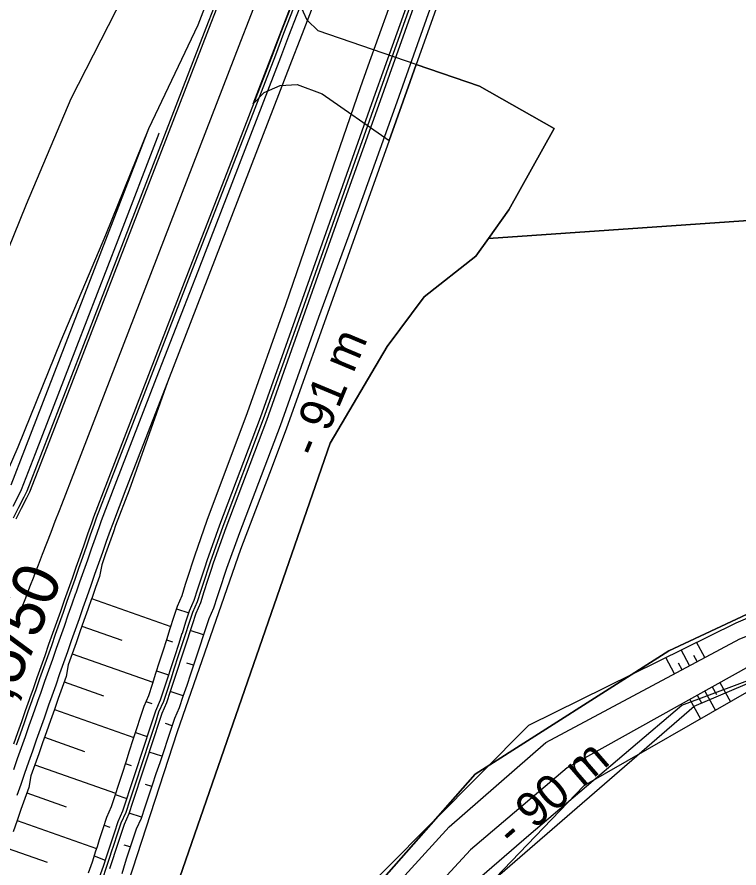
# Model space of a CAD drawing. Extents: x -440566 to -438466, y -1132677 to -1129707.
# Drawn here: x -439601.1 to -439538.1, y -1130370 to -1130295.8 of the extents above; entities that cross this region are included whole.
import ezdxf

# ---------------------------------------------------------------- set-up
doc = ezdxf.new("R2010")
doc.units = 0
for name, color, linetype in [('Vrstva 1', 7, 'Continuous'), ('Vrstva 10', 7, 'Continuous'), ('Vrstva 11', 7, 'Continuous'), ('Vrstva 15', 7, 'Continuous'), ('Vrstva 2', 7, 'Continuous'), ('Vrstva 3', 7, 'Continuous'), ('Vrstva 4', 7, 'Continuous'), ('Vrstva 52', 7, 'Continuous'), ('Vrstva 8', 7, 'Continuous'), ('Vrstva 9', 7, 'Continuous')]:
    doc.layers.add(name, color=color, linetype=linetype)

msp = doc.modelspace()

# ---------------------------------------------------------------- linework, layer by layer
at = {"layer": 'Vrstva 1'}
msp.add_circle((-439546.225, -1130326.068), 100.196, dxfattribs=at)
at = {"layer": 'Vrstva 10'}
for p, q in [((-439541.116, -1130351.662), (-439541.828, -1130350.33)), ((-439542.44, -1130352.37), (-439543.172, -1130350.994)), ((-439543.764, -1130353.076), (-439544.52, -1130351.66)), ((-439543.1, -1130352.722), (-439543.4, -1130352.166)), ((-439541.778, -1130352.016), (-439542.068, -1130351.474)), ((-439540.468, -1130354.218), (-439540.094, -1130354.89)), ((-439539.814, -1130353.854), (-439538.882, -1130355.522)), ((-439541.778, -1130354.95), (-439541.4, -1130355.626)), ((-439541.122, -1130354.586), (-439540.182, -1130356.268)), ((-439542.434, -1130355.318), (-439541.484, -1130357.014))]:
    msp.add_line(p, q, dxfattribs=at)
at = {"layer": 'Vrstva 11'}
for points in [[(-439614.54, -1130393.736), (-439602.886, -1130391.502), (-439590.194, -1130387.786), (-439581.31, -1130382.686), (-439571.73, -1130375.574), (-439563.408, -1130366.438), (-439554.968, -1130359.058), (-439538.066, -1130350.036), (-439518.176, -1130342.266)], [(-439517.844, -1130344.818), (-439537.232, -1130352.412), (-439553.102, -1130361.278), (-439561.554, -1130368.442), (-439569.834, -1130377.42), (-439579.582, -1130385.476), (-439589.25, -1130390.818), (-439602.494, -1130394.582), (-439614.18, -1130396.886)]]:
    msp.add_lwpolyline(points, dxfattribs=at)
at = {"layer": 'Vrstva 15'}
for p, q in [((-439594.569, -1130346.526), (-439587.676, -1130348.955)), ((-439587.182, -1130347.413), (-439586.104, -1130347.758)), ((-439595.418, -1130348.935), (-439591.938, -1130350.161)), ((-439584.822, -1130349.679), (-439585.975, -1130349.298)), ((-439588.05, -1130350.118), (-439587.518, -1130350.292)), ((-439596.268, -1130351.345), (-439589.241, -1130353.817)), ((-439585.701, -1130352.335), (-439586.272, -1130352.148)), ((-439588.92, -1130352.822), (-439587.869, -1130353.172)), ((-439596.972, -1130353.794), (-439593.544, -1130355.004)), ((-439586.581, -1130354.991), (-439587.713, -1130354.623)), ((-439589.842, -1130355.508), (-439589.322, -1130355.684)), ((-439597.821, -1130356.204), (-439590.902, -1130358.643)), ((-439587.56, -1130357.609), (-439588.119, -1130357.429)), ((-439598.67, -1130358.613), (-439595.18, -1130359.843)), ((-439590.757, -1130358.196), (-439589.735, -1130358.548)), ((-439588.445, -1130360.263), (-439589.552, -1130359.91)), ((-439599.52, -1130361.023), (-439592.479, -1130363.502)), ((-439591.633, -1130360.899), (-439591.129, -1130361.076)), ((-439589.331, -1130362.917), (-439589.879, -1130362.744)), ((-439600.224, -1130363.472), (-439596.792, -1130364.684)), ((-439592.511, -1130363.601), (-439591.515, -1130363.957)), ((-439590.22, -1130365.57), (-439591.304, -1130365.23)), ((-439601.073, -1130365.882), (-439594.152, -1130368.324)), ((-439593.481, -1130366.268), (-439592.991, -1130366.447)), ((-439601.922, -1130368.291), (-439598.444, -1130369.518)), ((-439591.206, -1130368.185), (-439591.741, -1130368.019)), ((-439594.363, -1130368.969), (-439593.397, -1130369.328))]:
    msp.add_line(p, q, dxfattribs=at)
at = {"layer": 'Vrstva 4'}
for points in [[(-439566.273, -1130299.951), (-439560.765, -1130301.836), (-439554.249, -1130305.538), (-439558.213, -1130312.615), (-439559.98, -1130315.123), (-439525.556, -1130312.748), (-439529.11, -1130305.49), (-439530.87, -1130301.89), (-439532.13, -1130291.95), (-439535.1, -1130272.62), (-439536.48, -1130264.88), (-439536.79, -1130262.95), (-439538.61, -1130253.25), (-439540.53, -1130243.61), (-439541.61, -1130240.34), (-439543.65, -1130245.48), (-439548.81, -1130256.72), (-439549.41, -1130258.02), (-439556.03, -1130271.21), (-439566.273, -1130299.951)], [(-439568.638, -1130306.589), (-439566.8, -1130301.43), (-439566.273, -1130299.951), (-439574.836, -1130297.021), (-439575.782, -1130296.084), (-439576.419, -1130294.674), (-439576.553, -1130293.141), (-439580.519, -1130303.402), (-439579.519, -1130302.403), (-439578.137, -1130301.772), (-439576.639, -1130301.685), (-439574.478, -1130302.52), (-439568.638, -1130306.589)], [(-439559.98, -1130315.123), (-439558.213, -1130312.615), (-439554.249, -1130305.538), (-439560.765, -1130301.836), (-439566.273, -1130299.951), (-439566.8, -1130301.43), (-439568.638, -1130306.589), (-439573.14, -1130319.23), (-439577.57, -1130331.65), (-439578.84, -1130335), (-439581.59, -1130342.25), (-439587.1, -1130358.13), (-439593.34, -1130377.27)], [(-439588.419, -1130375.264), (-439573.789, -1130332.956), (-439568.805, -1130324.53), (-439565.58, -1130320.223), (-439561.071, -1130316.673), (-439559.98, -1130315.123), (-439558.213, -1130312.615), (-439554.249, -1130305.538), (-439560.765, -1130301.836), (-439566.273, -1130299.951), (-439566.8, -1130301.43), (-439568.638, -1130306.589)], [(-439568.638, -1130306.589), (-439573.14, -1130319.23), (-439577.57, -1130331.65), (-439578.84, -1130335), (-439581.59, -1130342.25), (-439587.1, -1130358.13), (-439593.34, -1130377.27)], [(-439559.98, -1130315.123), (-439561.071, -1130316.673), (-439565.58, -1130320.223), (-439568.805, -1130324.53), (-439573.789, -1130332.956), (-439588.419, -1130375.264), (-439587.856, -1130378.814), (-439585.86, -1130381.827), (-439582.761, -1130383.539), (-439582.76, -1130383.539), (-439581.08, -1130382.59), (-439575.74, -1130378.42), (-439561.14, -1130361.82), (-439544.24, -1130351.07), (-439531.53, -1130345.11), (-439529.72, -1130344.26), (-439519.35, -1130339.39), (-439519.98, -1130330.32), (-439521.73, -1130320.56), (-439525.556, -1130312.748), (-439559.98, -1130315.123)], [(-439588.419, -1130375.264), (-439573.789, -1130332.956), (-439568.805, -1130324.53), (-439565.58, -1130320.223), (-439561.071, -1130316.673), (-439559.98, -1130315.123)], [(-439531.53, -1130345.11), (-439544.24, -1130351.07), (-439561.14, -1130361.82), (-439575.74, -1130378.42), (-439581.08, -1130382.59), (-439582.761, -1130383.539), (-439585.88, -1130385.3), (-439593.84, -1130388.2), (-439593.78, -1130392.68), (-439594.1, -1130393.57)], [(-439594.1, -1130393.57), (-439593.7, -1130393.5), (-439591.67, -1130392.84), (-439588.25, -1130391.525), (-439583.84, -1130389.83), (-439572.44, -1130382.24), (-439542.04, -1130355.91), (-439531.241, -1130351.299)]]:
    msp.add_lwpolyline(points, dxfattribs=at)
at = {"layer": 'Vrstva 52'}
msp.add_lwpolyline([(-439714.406, -1130412.208), (-439698.562, -1130412.132), (-439686.994, -1130411.394), (-439659.688, -1130406.848), (-439631.008, -1130400.752), (-439604.978, -1130396.618), (-439592.268, -1130393.564), (-439572.812, -1130381.312), (-439556.454, -1130367.154), (-439543.11, -1130355.814), (-439532.998, -1130352.028), (-439506.332, -1130342.096), (-439504.524, -1130343.242), (-439465.198, -1130328.028)], dxfattribs=at)
at = {"layer": 'Vrstva 8'}
for points in [[(-439577.979, -1130288.623), (-439580.863, -1130296.085), (-439581.584, -1130297.951), (-439585.189, -1130307.278), (-439588.795, -1130316.606), (-439592.4, -1130325.933), (-439596.005, -1130335.261), (-439597.194, -1130338.337), (-439597.397, -1130338.863), (-439597.765, -1130339.815), (-439598.133, -1130340.766), (-439598.501, -1130341.718), (-439598.869, -1130342.67), (-439599.237, -1130343.622), (-439599.605, -1130344.573), (-439599.61, -1130344.588), (-439599.973, -1130345.525), (-439600.34, -1130346.477), (-439600.708, -1130347.429), (-439601.076, -1130348.381)], [(-439574.947, -1130289.795), (-439577.831, -1130297.257), (-439578.553, -1130299.123), (-439582.158, -1130308.45), (-439585.763, -1130317.777), (-439589.368, -1130327.105), (-439592.974, -1130336.432), (-439594.163, -1130339.509), (-439594.35, -1130340.041), (-439594.69, -1130341.003), (-439595.029, -1130341.966), (-439595.368, -1130342.929), (-439595.708, -1130343.892), (-439596.047, -1130344.855), (-439596.386, -1130345.817), (-439596.391, -1130345.832), (-439596.726, -1130346.78), (-439597.065, -1130347.743), (-439597.404, -1130348.706), (-439597.744, -1130349.669), (-439598.083, -1130350.632), (-439598.422, -1130351.594), (-439598.762, -1130352.557), (-439599.101, -1130353.52), (-439599.44, -1130354.483), (-439599.717, -1130355.268), (-439599.78, -1130355.446), (-439600.119, -1130356.409), (-439600.458, -1130357.371), (-439600.798, -1130358.334), (-439601.137, -1130359.297)], [(-439575.18, -1130289.705), (-439578.065, -1130297.167), (-439578.786, -1130299.032), (-439582.391, -1130308.36), (-439585.996, -1130317.687), (-439589.602, -1130327.015), (-439593.207, -1130336.342), (-439594.396, -1130339.419), (-439594.583, -1130339.95), (-439594.923, -1130340.913), (-439595.262, -1130341.876), (-439595.601, -1130342.839), (-439595.941, -1130343.802), (-439596.28, -1130344.765)], [(-439601.36, -1130361.431), (-439601.02, -1130360.468), (-439600.681, -1130359.506), (-439600.342, -1130358.543), (-439600.002, -1130357.58), (-439599.663, -1130356.617), (-439599.324, -1130355.654), (-439599.261, -1130355.476), (-439598.984, -1130354.692), (-439598.645, -1130353.729), (-439598.306, -1130352.766), (-439597.966, -1130351.803), (-439597.627, -1130350.84), (-439597.288, -1130349.877), (-439596.948, -1130348.915), (-439596.609, -1130347.952), (-439596.27, -1130346.989), (-439595.935, -1130346.041), (-439595.93, -1130346.026), (-439595.591, -1130345.063), (-439595.252, -1130344.101), (-439594.912, -1130343.138), (-439594.573, -1130342.175), (-439594.234, -1130341.212), (-439593.894, -1130340.249), (-439593.702, -1130339.703), (-439592.507, -1130336.613), (-439588.902, -1130327.285), (-439585.297, -1130317.958), (-439581.691, -1130308.63), (-439578.086, -1130299.303), (-439577.365, -1130297.437), (-439574.481, -1130289.975)], [(-439573.548, -1130290.336), (-439576.432, -1130297.798), (-439577.153, -1130299.663), (-439580.759, -1130308.991), (-439584.364, -1130318.318)], [(-439567.787, -1130292.563), (-439570.478, -1130300.099), (-439571.151, -1130301.984), (-439574.419, -1130311.441), (-439577.66, -1130320.91), (-439581.001, -1130330.339), (-439584.519, -1130339.7), (-439585.609, -1130342.815), (-439585.78, -1130343.353), (-439586.092, -1130344.327), (-439586.403, -1130345.3), (-439586.715, -1130346.274), (-439587.117, -1130347.212), (-439587.429, -1130348.185), (-439587.742, -1130349.159), (-439587.747, -1130349.174), (-439588.054, -1130350.132), (-439588.367, -1130351.105), (-439588.68, -1130352.078), (-439588.994, -1130353.051), (-439589.307, -1130354.024), (-439589.621, -1130354.996)], [(-439566.491, -1130293.064), (-439569.17, -1130300.605), (-439569.84, -1130302.49), (-439573.19, -1130311.916), (-439576.54, -1130321.343), (-439579.889, -1130330.769), (-439583.425, -1130340.123), (-439584.53, -1130343.232), (-439584.704, -1130343.769), (-439585.019, -1130344.741), (-439585.335, -1130345.713), (-439585.65, -1130346.685), (-439586.059, -1130347.621), (-439586.376, -1130348.593), (-439586.692, -1130349.565), (-439586.697, -1130349.58), (-439587.009, -1130350.536), (-439587.325, -1130351.508), (-439587.643, -1130352.479), (-439587.96, -1130353.45), (-439588.277, -1130354.422), (-439588.595, -1130355.393), (-439589.007, -1130356.328), (-439589.325, -1130357.299), (-439589.644, -1130358.269), (-439589.904, -1130359.061), (-439589.962, -1130359.24), (-439590.281, -1130360.211), (-439590.601, -1130361.181), (-439590.92, -1130362.152)], [(-439566.211, -1130293.172), (-439568.891, -1130300.713), (-439569.561, -1130302.598), (-439572.91, -1130312.024), (-439576.26, -1130321.451), (-439579.609, -1130330.877), (-439583.146, -1130340.231), (-439584.25, -1130343.34), (-439584.424, -1130343.877), (-439584.739, -1130344.849), (-439585.055, -1130345.821), (-439585.37, -1130346.793), (-439585.78, -1130347.729), (-439586.096, -1130348.701), (-439586.412, -1130349.673), (-439586.417, -1130349.688), (-439586.729, -1130350.644), (-439587.046, -1130351.616), (-439587.363, -1130352.587), (-439587.68, -1130353.559), (-439587.998, -1130354.53), (-439588.315, -1130355.501), (-439588.727, -1130356.436), (-439589.045, -1130357.407), (-439589.364, -1130358.378), (-439589.624, -1130359.169), (-439589.683, -1130359.348), (-439590.002, -1130360.319), (-439590.321, -1130361.29), (-439590.64, -1130362.26)], [(-439565.931, -1130293.28), (-439568.611, -1130300.821), (-439569.281, -1130302.706), (-439572.63, -1130312.133), (-439575.98, -1130321.559), (-439579.33, -1130330.985), (-439582.866, -1130340.339), (-439583.97, -1130343.448), (-439584.144, -1130343.985), (-439584.46, -1130344.957), (-439584.775, -1130345.93), (-439585.091, -1130346.902), (-439585.5, -1130347.837), (-439585.816, -1130348.809), (-439586.132, -1130349.781), (-439586.137, -1130349.796), (-439586.449, -1130350.752), (-439586.766, -1130351.724), (-439587.083, -1130352.695), (-439587.4, -1130353.667), (-439587.718, -1130354.638), (-439588.036, -1130355.609), (-439588.447, -1130356.544), (-439588.765, -1130357.515), (-439589.084, -1130358.486), (-439589.344, -1130359.277), (-439589.403, -1130359.457), (-439589.722, -1130360.427), (-439590.041, -1130361.398), (-439590.361, -1130362.368)], [(-439591.827, -1130293.992), (-439596.382, -1130302.952), (-439600.271, -1130312.17), (-439604.065, -1130321.424)], [(-439564.615, -1130293.789), (-439567.284, -1130301.334), (-439567.951, -1130303.22), (-439571.341, -1130312.631), (-439574.779, -1130322.023), (-439578.135, -1130331.447), (-439581.687, -1130340.795), (-439582.808, -1130343.898), (-439582.984, -1130344.434), (-439583.303, -1130345.404), (-439583.623, -1130346.375), (-439583.943, -1130347.345), (-439584.359, -1130348.278), (-439584.679, -1130349.248), (-439585, -1130350.219), (-439585.005, -1130350.234), (-439585.321, -1130351.188), (-439585.642, -1130352.158), (-439585.963, -1130353.128), (-439586.285, -1130354.098), (-439586.607, -1130355.067), (-439586.929, -1130356.037), (-439587.347, -1130356.969), (-439587.67, -1130357.938), (-439587.993, -1130358.908), (-439588.256, -1130359.698), (-439588.316, -1130359.877), (-439588.639, -1130360.846), (-439588.963, -1130361.815), (-439589.287, -1130362.783), (-439589.611, -1130363.752), (-439589.935, -1130364.721), (-439590.26, -1130365.689), (-439590.681, -1130366.62), (-439591.006, -1130367.589), (-439591.331, -1130368.557), (-439591.527, -1130369.155), (-439591.638, -1130369.532), (-439591.927, -1130370.515)], [(-439583.894, -1130294.914), (-439584.615, -1130296.779), (-439588.221, -1130306.107), (-439591.826, -1130315.434), (-439595.431, -1130324.762), (-439599.037, -1130334.089), (-439600.226, -1130337.165), (-439600.481, -1130337.671), (-439600.944, -1130338.586), (-439601.408, -1130339.501)], [(-439583.661, -1130295.004), (-439584.382, -1130296.869), (-439587.988, -1130306.197), (-439591.593, -1130315.524), (-439595.198, -1130324.852), (-439598.803, -1130334.179), (-439599.992, -1130337.255), (-439600.248, -1130337.761), (-439600.711, -1130338.676), (-439601.174, -1130339.591)], [(-439584.594, -1130294.643), (-439585.315, -1130296.509), (-439589.62, -1130305.566), (-439593.225, -1130314.893)], [(-439589.62, -1130305.566), (-439593.365, -1130314.839), (-439597.25, -1130324.058), (-439600.995, -1130333.332), (-439602.324, -1130336.354)], [(-439588.693, -1130305.946), (-439588.701, -1130305.961), (-439592.292, -1130315.254), (-439595.898, -1130324.581), (-439599.503, -1130333.909), (-439600.71, -1130337.031), (-439600.988, -1130337.582), (-439601.451, -1130338.497)], [(-439593.225, -1130314.893), (-439596.83, -1130324.221), (-439600.436, -1130333.548), (-439601.625, -1130336.624)], [(-439584.364, -1130318.318), (-439587.969, -1130327.646), (-439591.575, -1130336.973), (-439592.764, -1130340.049), (-439592.951, -1130340.581), (-439593.29, -1130341.544), (-439593.63, -1130342.507), (-439593.969, -1130343.47), (-439594.308, -1130344.433), (-439594.648, -1130345.395), (-439594.987, -1130346.358), (-439594.992, -1130346.373), (-439595.326, -1130347.321), (-439595.666, -1130348.284), (-439596.005, -1130349.247), (-439596.344, -1130350.21), (-439596.684, -1130351.172), (-439597.023, -1130352.135), (-439597.362, -1130353.098), (-439597.702, -1130354.061), (-439598.041, -1130355.024), (-439598.318, -1130355.809), (-439598.38, -1130355.986), (-439598.72, -1130356.949), (-439599.059, -1130357.912), (-439599.398, -1130358.875), (-439599.738, -1130359.838), (-439600.077, -1130360.801), (-439600.416, -1130361.763), (-439600.756, -1130362.726), (-439601.095, -1130363.689)], [(-439587.969, -1130327.646), (-439591.295, -1130337.081), (-439592.484, -1130340.158), (-439592.671, -1130340.69), (-439593.011, -1130341.652), (-439593.35, -1130342.615), (-439593.689, -1130343.578), (-439593.889, -1130344.595), (-439594.228, -1130345.558), (-439594.567, -1130346.521), (-439594.573, -1130346.535), (-439594.907, -1130347.483), (-439595.246, -1130348.446), (-439595.585, -1130349.409), (-439595.925, -1130350.372), (-439596.264, -1130351.335), (-439596.603, -1130352.297), (-439596.803, -1130353.314), (-439597.142, -1130354.277), (-439597.481, -1130355.24), (-439597.758, -1130356.025), (-439597.821, -1130356.203), (-439598.16, -1130357.166), (-439598.499, -1130358.128), (-439598.839, -1130359.091), (-439599.178, -1130360.054), (-439599.517, -1130361.017), (-439599.857, -1130361.98), (-439600.056, -1130362.997), (-439600.395, -1130363.959), (-439600.735, -1130364.922), (-439600.944, -1130365.515), (-439601.074, -1130365.885), (-439601.413, -1130366.848)], [(-439596.28, -1130344.765), (-439596.619, -1130345.727), (-439596.625, -1130345.742), (-439596.959, -1130346.69), (-439597.298, -1130347.653), (-439597.637, -1130348.616), (-439597.977, -1130349.579), (-439598.316, -1130350.541), (-439598.655, -1130351.504), (-439598.995, -1130352.467), (-439599.334, -1130353.43), (-439599.673, -1130354.393), (-439599.95, -1130355.178), (-439600.013, -1130355.356), (-439600.352, -1130356.318), (-439600.691, -1130357.281), (-439601.031, -1130358.244), (-439601.37, -1130359.207)], [(-439589.621, -1130354.996), (-439590.026, -1130355.934), (-439590.34, -1130356.906), (-439590.655, -1130357.879), (-439590.911, -1130358.672), (-439590.969, -1130358.851), (-439591.284, -1130359.823), (-439591.6, -1130360.795), (-439591.915, -1130361.767), (-439592.231, -1130362.739), (-439592.547, -1130363.711), (-439592.863, -1130364.683), (-439593.27, -1130365.62), (-439593.586, -1130366.591), (-439593.903, -1130367.563), (-439594.098, -1130368.161), (-439594.22, -1130368.534), (-439594.538, -1130369.506), (-439594.868, -1130370.472)], [(-439590.92, -1130362.152), (-439591.24, -1130363.122), (-439591.56, -1130364.093), (-439591.88, -1130365.063), (-439592.294, -1130365.997), (-439592.615, -1130366.967), (-439592.936, -1130367.937), (-439593.133, -1130368.534), (-439593.257, -1130368.907), (-439593.578, -1130369.876), (-439593.9, -1130370.846)], [(-439590.64, -1130362.26), (-439590.96, -1130363.23), (-439591.28, -1130364.201), (-439591.6, -1130365.171), (-439592.014, -1130366.105), (-439592.335, -1130367.075), (-439592.656, -1130368.045), (-439592.854, -1130368.642), (-439592.977, -1130369.015), (-439593.299, -1130369.984), (-439593.62, -1130370.954)], [(-439590.361, -1130362.368), (-439590.68, -1130363.339), (-439591, -1130364.309), (-439591.321, -1130365.279), (-439591.734, -1130366.213), (-439592.055, -1130367.183), (-439592.376, -1130368.153), (-439592.574, -1130368.75), (-439592.697, -1130369.123), (-439593.019, -1130370.093)]]:
    msp.add_lwpolyline(points, dxfattribs=at)
at = {"layer": 'Vrstva 9'}
for points in [[(-439614.54, -1130393.736), (-439603.236, -1130390.488), (-439590.542, -1130386.564), (-439573.232, -1130374.44), (-439556.462, -1130357.56), (-439538.37, -1130348.624), (-439517.466, -1130339.712)], [(-439517.528, -1130346.522), (-439536.884, -1130354.376), (-439551.674, -1130362.86), (-439567.784, -1130379.662), (-439588.862, -1130392.166), (-439602.298, -1130395.778), (-439614.18, -1130396.886)]]:
    msp.add_lwpolyline(points, dxfattribs=at)

# ---------------------------------------------------------------- texts
at = {"layer": 'Vrstva 2'}
msp.add_text('S 7,5/50', height=4, rotation=67.52057, dxfattribs=at).set_placement((-439604.675, -1130363.042))
at = {"layer": 'Vrstva 3'}
for s, rotation, p in [('- 91 m', 67.3071, (-439574.86, -1130334.345)), ('- 90 m', 40.8752, (-439557.843, -1130368.298))]:
    msp.add_text(s, height=3, rotation=rotation, dxfattribs=at).set_placement(p)

doc.saveas('drawing.dxf')
